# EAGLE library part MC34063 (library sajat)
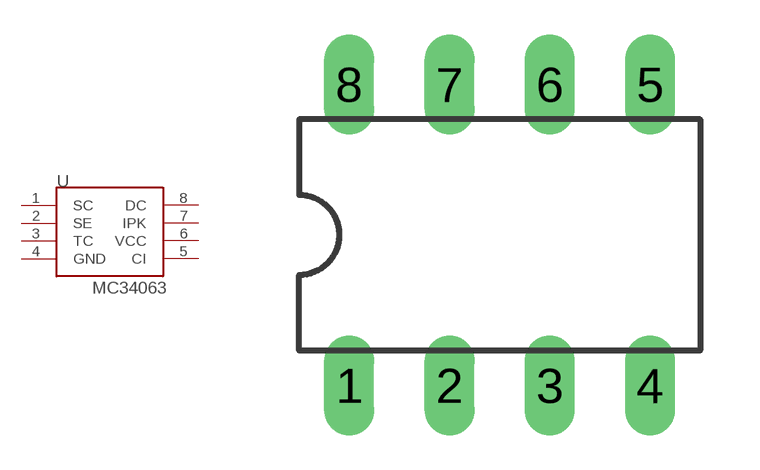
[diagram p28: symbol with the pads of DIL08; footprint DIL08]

Designator prefix -

## MC34063  [DIL08]
1  SC
2  SE
3  TC
4  GND
5  CI
6  VCC
7  IPK
8  DC

## Footprint DIL08 (pad centres in mm)
Dual In Line Package
drill 0.5 pad 1.27 long: 1 -3.81,-3.81; 2 -1.27,-3.81; 3 1.27,-3.81; 4 3.81,-3.81; 5 3.81,3.81; 6 1.27,3.81; 7 -1.27,3.81; 8 -3.81,3.81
